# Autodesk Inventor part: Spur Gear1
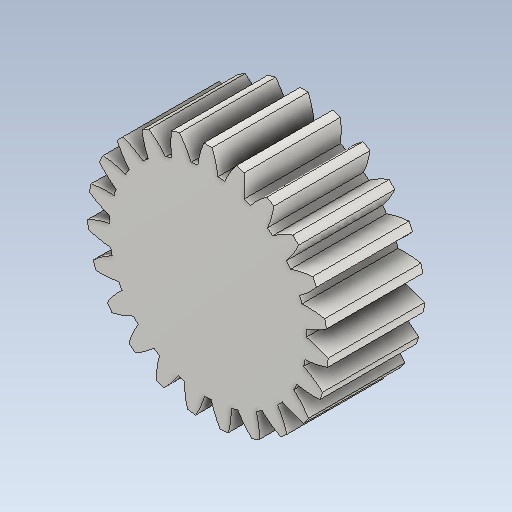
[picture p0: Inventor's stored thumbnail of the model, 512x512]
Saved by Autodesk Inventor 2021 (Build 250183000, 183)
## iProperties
Created: 2026-10
Part Number: Spur Gear1
Material: Steel
Document SubType Name: Modeling
Designer: hp
Categories: <?xml version="1.0" encoding="UTF-16"?> <MemberInstance><Categories><FamilyTemplate><FamilyTemplateParameter ValueType="xs:double" Id="1" ObjectReferenceKey="da
Density: 1 g/cm^3
Appearance: Steel
CustomPartVersion: 1
Author: hp
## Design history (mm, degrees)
sketch "Sketch1"
  geometry: C1 r 25 at (0, 0)
  constraints: 1 centre point
  dimensions: "d0" = 50 diameter of C1 (= da_da)
extrude "Extrusion1" new body sketch "Sketch1" distance "d1" = 20 (= da_b); taper "d2" = 0 deg
workplane "Work Plane2"
sketch "Sketch2"
  geometry: C1 r 25 at (0, 0) reference; C2 r 23 at (0, 0)
  constraints: 1 centre point, 1 coincident
  dimensions: "d3" = 46 diameter of C2 (= da_d)
feature "Pitch Diameter" sketch "Sketch2" dims "d4" = 10, "d5" = 0
workplane "Work Plane8"
workplane "Work Plane9"
feature "Spur Gear" dims "d5" = 0, "da_b" = 20, "da_d" = 46, "da_aw" = 80, "da_da" = 50, "da_df" = 41, "da_dw" = 46, angle "da_beta" = 0 deg, "da_lefttooth" = 0, "da_righttooth" = 0
body "Solid1"
body "Srf1"
other parameters: "d17" = 0, "d34" = 1.36591 (computed from da_z), "d39" = 0, "d41" = 0, "d47" = 0, "d48" = 0
